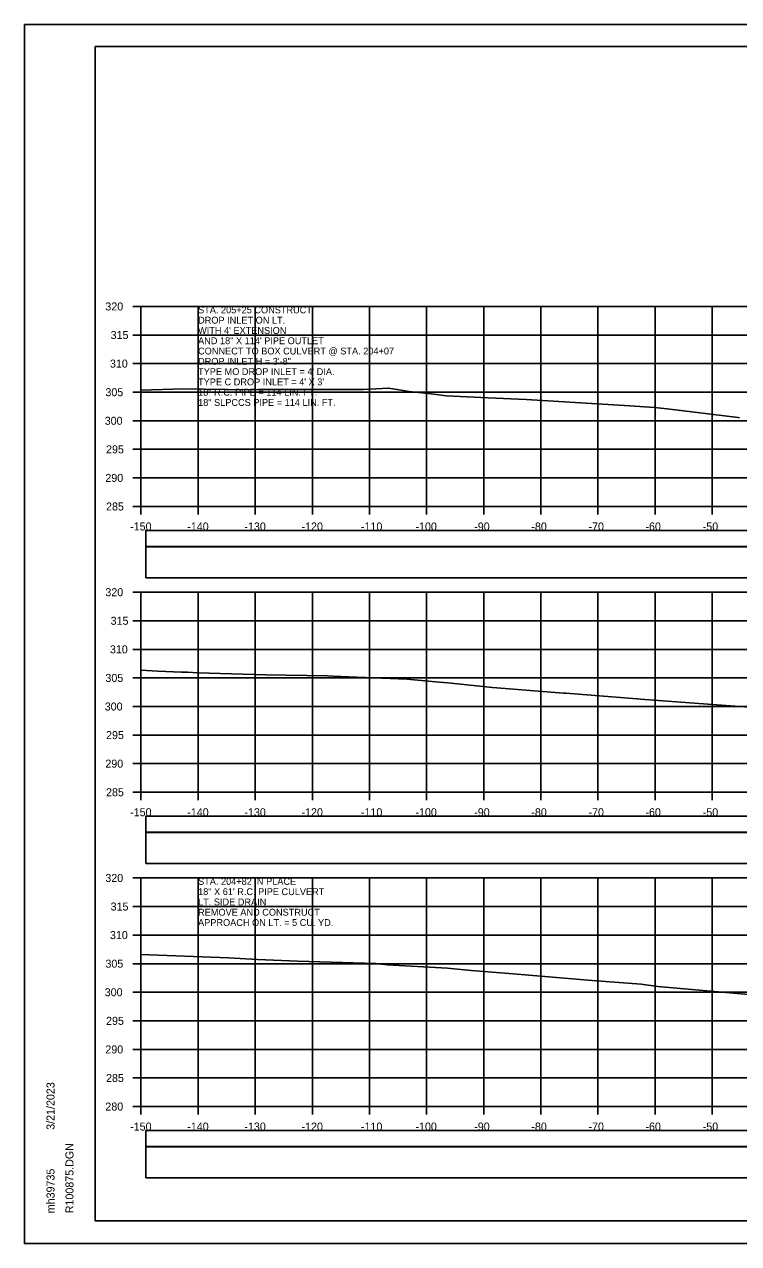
# Model space of a CAD drawing. Extents: x 1368122 to 1710785, y 373130 to 557566.
# Drawn here: x 1369851.8 to 1369976.9, y 373983.7 to 374197 of the extents above; entities that cross this region are included whole.
import ezdxf

# ---------------------------------------------------------------- set-up
doc = ezdxf.new("R2010")
doc.units = 0
for name, color, linetype in [('R_Axis', 7, 'Continuous'), ('R_Axis Annot', 7, 'Continuous'), ('R_Border', 7, 'Continuous'), ('R_Exist Surface', 7, 'Continuous'), ('R_Grid', 7, 'Continuous'), ('R_No Plot', 7, 'Continuous'), ('R_Water Annot', 7, 'Continuous')]:
    doc.layers.add(name, color=color, linetype=linetype)

msp = doc.modelspace()

# ---------------------------------------------------------------- linework, layer by layer
for points in [[(1369873.09, 374105.65), (1370171.39, 374105.65), (1370171.39, 374108.47), (1369873.09, 374108.47)], [(1369873.09, 374100.19), (1370171.39, 374100.19), (1370171.39, 374105.6), (1369873.09, 374105.6)], [(1369873.09, 374055.65), (1370171.39, 374055.65), (1370171.39, 374058.47), (1369873.09, 374058.47)], [(1369873.09, 374050.19), (1370171.39, 374050.19), (1370171.39, 374055.6), (1369873.09, 374055.6)], [(1369873.09, 374000.65), (1370171.39, 374000.65), (1370171.39, 374003.47), (1369873.09, 374003.47)], [(1369873.09, 373995.19), (1370171.39, 373995.19), (1370171.39, 374000.6), (1369873.09, 374000.6)]]:
    msp.add_lwpolyline(points, close=True)
at = {"layer": 'R_Axis'}
for p, q in [((1369870.84, 374147.66), (1369872.24, 374147.66)), ((1369872.24, 374112.66), (1369872.24, 374147.66)), ((1369870.84, 374142.66), (1369872.24, 374142.66)), ((1369870.84, 374137.66), (1369872.24, 374137.66)), ((1369870.84, 374132.66), (1369872.24, 374132.66)), ((1369870.84, 374127.66), (1369872.24, 374127.66)), ((1369870.84, 374122.66), (1369872.24, 374122.66)), ((1369870.84, 374117.66), (1369872.24, 374117.66)), ((1369870.84, 374112.66), (1369872.24, 374112.66)), ((1369872.24, 374112.66), (1370172.24, 374112.66)), ((1369872.24, 374111.26), (1369872.24, 374112.66)), ((1369882.24, 374111.26), (1369882.24, 374112.66)), ((1369892.24, 374111.26), (1369892.24, 374112.66)), ((1369902.24, 374111.26), (1369902.24, 374112.66)), ((1369912.24, 374111.26), (1369912.24, 374112.66)), ((1369922.24, 374111.26), (1369922.24, 374112.66)), ((1369932.24, 374111.26), (1369932.24, 374112.66)), ((1369942.24, 374111.26), (1369942.24, 374112.66)), ((1369952.24, 374111.26), (1369952.24, 374112.66)), ((1369962.24, 374111.26), (1369962.24, 374112.66)), ((1369972.24, 374111.26), (1369972.24, 374112.66)), ((1369870.84, 374097.66), (1369872.24, 374097.66)), ((1369872.24, 374062.66), (1369872.24, 374097.66)), ((1369870.84, 374092.66), (1369872.24, 374092.66)), ((1369870.84, 374087.66), (1369872.24, 374087.66)), ((1369870.84, 374082.66), (1369872.24, 374082.66)), ((1369870.84, 374077.66), (1369872.24, 374077.66)), ((1369870.84, 374072.66), (1369872.24, 374072.66)), ((1369870.84, 374067.66), (1369872.24, 374067.66)), ((1369870.84, 374062.66), (1369872.24, 374062.66)), ((1369872.24, 374062.66), (1370172.24, 374062.66)), ((1369872.24, 374061.26), (1369872.24, 374062.66)), ((1369882.24, 374061.26), (1369882.24, 374062.66)), ((1369892.24, 374061.26), (1369892.24, 374062.66)), ((1369902.24, 374061.26), (1369902.24, 374062.66)), ((1369912.24, 374061.26), (1369912.24, 374062.66)), ((1369922.24, 374061.26), (1369922.24, 374062.66)), ((1369932.24, 374061.26), (1369932.24, 374062.66)), ((1369942.24, 374061.26), (1369942.24, 374062.66)), ((1369952.24, 374061.26), (1369952.24, 374062.66)), ((1369962.24, 374061.26), (1369962.24, 374062.66)), ((1369972.24, 374061.26), (1369972.24, 374062.66)), ((1369870.84, 374047.66), (1369872.24, 374047.66)), ((1369872.24, 374007.66), (1369872.24, 374047.66)), ((1369870.84, 374042.66), (1369872.24, 374042.66)), ((1369870.84, 374037.66), (1369872.24, 374037.66)), ((1369870.84, 374032.66), (1369872.24, 374032.66)), ((1369870.84, 374027.66), (1369872.24, 374027.66)), ((1369870.84, 374022.66), (1369872.24, 374022.66)), ((1369870.84, 374017.66), (1369872.24, 374017.66)), ((1369870.84, 374012.66), (1369872.24, 374012.66)), ((1369870.84, 374007.66), (1369872.24, 374007.66)), ((1369872.24, 374007.66), (1370172.24, 374007.66)), ((1369872.24, 374006.26), (1369872.24, 374007.66)), ((1369882.24, 374006.26), (1369882.24, 374007.66)), ((1369892.24, 374006.26), (1369892.24, 374007.66)), ((1369902.24, 374006.26), (1369902.24, 374007.66)), ((1369912.24, 374006.26), (1369912.24, 374007.66)), ((1369922.24, 374006.26), (1369922.24, 374007.66)), ((1369932.24, 374006.26), (1369932.24, 374007.66)), ((1369942.24, 374006.26), (1369942.24, 374007.66)), ((1369952.24, 374006.26), (1369952.24, 374007.66)), ((1369962.24, 374006.26), (1369962.24, 374007.66)), ((1369972.24, 374006.26), (1369972.24, 374007.66))]:
    msp.add_line(p, q, dxfattribs=at)
at = {"layer": 'R_Border'}
for p, q in [((1369864.24, 374193.12), (1370180.42, 374193.12)), ((1369864.24, 373987.66), (1369864.24, 374193.12)), ((1369864.24, 373987.66), (1369864.24, 373987.66)), ((1370180.42, 373987.66), (1369864.24, 373987.66))]:
    msp.add_line(p, q, dxfattribs=at)
at = {"layer": 'R_Exist Surface'}
for points in [[(1369872.24, 374133.01), (1369879.72, 374133.24), (1369890.47, 374133.06), (1369892.77, 374133.1), (1369895.66, 374133.14), (1369907.83, 374133.12), (1369910.07, 374133.13), (1369910.57, 374133.12), (1369911.14, 374133.14), (1369915.58, 374133.38), (1369917.07, 374133.1), (1369919.19, 374132.76), (1369923.02, 374132.36), (1369925.67, 374132.04), (1369933.04, 374131.7), (1369939.66, 374131.38), (1369947.34, 374130.94), (1369957.8, 374130.3), (1369962.12, 374130), (1369964.38, 374129.75), (1369976.8, 374128.21), (1369977.02, 374128.17)], [(1369872.24, 374084), (1369875.22, 374083.87), (1369879.32, 374083.69), (1369880.14, 374083.68), (1369880.39, 374083.66), (1369882.2, 374083.58), (1369890.07, 374083.34), (1369894.05, 374083.21), (1369904.87, 374083.02), (1369905.91, 374082.94), (1369914.32, 374082.62), (1369918.86, 374082.47), (1369924.43, 374081.89), (1369925.97, 374081.8), (1369933.77, 374080.97), (1369946.18, 374080.01), (1369946.63, 374079.97), (1369959.1, 374079), (1369959.18, 374078.99), (1369959.67, 374078.95), (1369974.63, 374077.81), (1369978.79, 374077.52)], [(1369872.24, 374034.26), (1369887.56, 374033.69), (1369892.66, 374033.4), (1369899.65, 374033.12), (1369913.38, 374032.67), (1369915.34, 374032.47), (1369925.91, 374031.89), (1369930.07, 374031.44), (1369936.69, 374030.93), (1369951.22, 374029.72), (1369959.79, 374029.05), (1369962.73, 374028.64), (1369979.92, 374027.15)]]:
    msp.add_lwpolyline(points, dxfattribs=at)
at = {"layer": 'R_Grid'}
for p, q in [((1369872.24, 374147.66), (1370172.24, 374147.66)), ((1369872.24, 374112.66), (1369872.24, 374147.66)), ((1369882.24, 374112.66), (1369882.24, 374147.66)), ((1369892.24, 374112.66), (1369892.24, 374147.66)), ((1369902.24, 374112.66), (1369902.24, 374147.66)), ((1369912.24, 374112.66), (1369912.24, 374147.66)), ((1369922.24, 374112.66), (1369922.24, 374147.66)), ((1369932.24, 374112.66), (1369932.24, 374147.66)), ((1369942.24, 374112.66), (1369942.24, 374147.66)), ((1369952.24, 374112.66), (1369952.24, 374147.66)), ((1369962.24, 374112.66), (1369962.24, 374147.66)), ((1369972.24, 374112.66), (1369972.24, 374147.66)), ((1369872.24, 374142.66), (1370172.24, 374142.66)), ((1369872.24, 374137.66), (1370172.24, 374137.66)), ((1369872.24, 374132.66), (1370172.24, 374132.66)), ((1369872.24, 374127.66), (1370172.24, 374127.66)), ((1369872.24, 374122.66), (1370172.24, 374122.66)), ((1369872.24, 374117.66), (1370172.24, 374117.66)), ((1369872.24, 374112.66), (1370172.24, 374112.66)), ((1369872.24, 374097.66), (1370172.24, 374097.66)), ((1369872.24, 374062.66), (1369872.24, 374097.66)), ((1369882.24, 374062.66), (1369882.24, 374097.66)), ((1369892.24, 374062.66), (1369892.24, 374097.66)), ((1369902.24, 374062.66), (1369902.24, 374097.66)), ((1369912.24, 374062.66), (1369912.24, 374097.66)), ((1369922.24, 374062.66), (1369922.24, 374097.66)), ((1369932.24, 374062.66), (1369932.24, 374097.66)), ((1369942.24, 374062.66), (1369942.24, 374097.66)), ((1369952.24, 374062.66), (1369952.24, 374097.66)), ((1369962.24, 374062.66), (1369962.24, 374097.66)), ((1369972.24, 374062.66), (1369972.24, 374097.66)), ((1369872.24, 374092.66), (1370172.24, 374092.66)), ((1369872.24, 374087.66), (1370172.24, 374087.66)), ((1369872.24, 374082.66), (1370172.24, 374082.66)), ((1369872.24, 374077.66), (1370172.24, 374077.66)), ((1369872.24, 374072.66), (1370172.24, 374072.66)), ((1369872.24, 374067.66), (1370172.24, 374067.66)), ((1369872.24, 374062.66), (1370172.24, 374062.66)), ((1369872.24, 374047.66), (1370172.24, 374047.66)), ((1369872.24, 374007.66), (1369872.24, 374047.66)), ((1369882.24, 374007.66), (1369882.24, 374047.66)), ((1369892.24, 374007.66), (1369892.24, 374047.66)), ((1369902.24, 374007.66), (1369902.24, 374047.66)), ((1369912.24, 374007.66), (1369912.24, 374047.66)), ((1369922.24, 374007.66), (1369922.24, 374047.66)), ((1369932.24, 374007.66), (1369932.24, 374047.66)), ((1369942.24, 374007.66), (1369942.24, 374047.66)), ((1369952.24, 374007.66), (1369952.24, 374047.66)), ((1369962.24, 374007.66), (1369962.24, 374047.66)), ((1369972.24, 374007.66), (1369972.24, 374047.66)), ((1369872.24, 374042.66), (1370172.24, 374042.66)), ((1369872.24, 374037.66), (1370172.24, 374037.66)), ((1369872.24, 374032.66), (1370172.24, 374032.66)), ((1369872.24, 374027.66), (1370172.24, 374027.66)), ((1369872.24, 374022.66), (1370172.24, 374022.66)), ((1369872.24, 374017.66), (1370172.24, 374017.66)), ((1369872.24, 374012.66), (1370172.24, 374012.66)), ((1369872.24, 374007.66), (1370172.24, 374007.66))]:
    msp.add_line(p, q, dxfattribs=at)
at = {"layer": 'R_No Plot'}
for p, q in [((1369851.84, 374197.02), (1370185.17, 374197.02)), ((1369851.84, 373983.68), (1370185.17, 373983.68))]:
    msp.add_line(p, q, dxfattribs=at)
for points in [[(1369851.83, 374197.02), (1370185.17, 374197.02), (1370185.17, 373983.68), (1369851.83, 373983.68)], [(1370098.16, 374193.12), (1370117.78, 374193.12), (1370117.78, 374183.24), (1370133.89, 374183.24), (1370157.09, 374183.24), (1370157.21, 374155.08), (1370180.42, 374155.08), (1370180.42, 373987.66), (1369864.24, 373987.66), (1369864.24, 374193.12)]]:
    msp.add_lwpolyline(points, close=True, dxfattribs=at)

# ---------------------------------------------------------------- texts
at = {"layer": 'R_Axis Annot'}
for s, p in [('320', (1369866.01, 374146.96)), ('315', (1369866.93, 374141.96)), ('310', (1369866.81, 374136.96)), ('305', (1369866.02, 374131.96)), ('300', (1369865.9, 374126.96)), ('295', (1369866.13, 374121.96)), ('290', (1369866.01, 374116.96)), ('285', (1369866.13, 374111.96)), ('-150', (1369870.35, 374108.46)), ('-140', (1369880.35, 374108.46)), ('-130', (1369890.35, 374108.46)), ('-120', (1369900.35, 374108.46)), ('-110', (1369910.75, 374108.46)), ('-100', (1369920.29, 374108.46)), ('-90', (1369930.58, 374108.46)), ('-80', (1369940.58, 374108.46)), ('-70', (1369950.58, 374108.46)), ('-60', (1369960.55, 374108.46)), ('-50', (1369970.58, 374108.46)), ('320', (1369866.01, 374096.96)), ('315', (1369866.93, 374091.96)), ('310', (1369866.81, 374086.96)), ('305', (1369866.02, 374081.96)), ('300', (1369865.9, 374076.96)), ('295', (1369866.13, 374071.96)), ('290', (1369866.01, 374066.96)), ('285', (1369866.13, 374061.96)), ('-150', (1369870.35, 374058.46)), ('-140', (1369880.35, 374058.46)), ('-130', (1369890.35, 374058.46)), ('-120', (1369900.35, 374058.46)), ('-110', (1369910.75, 374058.46)), ('-100', (1369920.29, 374058.46)), ('-90', (1369930.58, 374058.46)), ('-80', (1369940.58, 374058.46)), ('-70', (1369950.58, 374058.46)), ('-60', (1369960.55, 374058.46)), ('-50', (1369970.58, 374058.46)), ('320', (1369866.01, 374046.96)), ('315', (1369866.93, 374041.96)), ('310', (1369866.81, 374036.96)), ('305', (1369866.02, 374031.96)), ('300', (1369865.9, 374026.96)), ('295', (1369866.13, 374021.96)), ('290', (1369866.01, 374016.96)), ('285', (1369866.13, 374011.96)), ('280', (1369866.01, 374006.96)), ('-150', (1369870.35, 374003.46)), ('-140', (1369880.35, 374003.46)), ('-130', (1369890.35, 374003.46)), ('-120', (1369900.35, 374003.46)), ('-110', (1369910.75, 374003.46)), ('-100', (1369920.29, 374003.46)), ('-90', (1369930.58, 374003.46)), ('-80', (1369940.58, 374003.46)), ('-70', (1369950.58, 374003.46)), ('-60', (1369960.55, 374003.46)), ('-50', (1369970.58, 374003.46))]:
    msp.add_text(s, height=1.4, dxfattribs=at).set_placement(p)
at = {"layer": 'R_Border'}
for s, p in [('3/21/2023', (1369857.11, 374003.59)), ('R100875.DGN', (1369860.43, 373988.99)), ('mh39735', (1369857.11, 373988.99))]:
    msp.add_text(s, height=1.4, rotation=90, dxfattribs=at).set_placement(p)
at = {"layer": 'R_Water Annot'}
for s, p in [('STA. 205+25 CONSTRUCT', (1369882.24, 374146.46)), ('DROP INLET ON LT.', (1369882.24, 374144.66)), ("WITH 4' EXTENSION", (1369882.24, 374142.86)), ('AND 18" X 114\' PIPE OUTLET', (1369882.24, 374141.06)), ('CONNECT TO BOX CULVERT @ STA. 204+07', (1369882.24, 374139.26)), ("TYPE MO DROP INLET = 4' DIA.", (1369882.24, 374135.66)), ('DROP INLET H = 3\'-8"', (1369882.24, 374137.46)), ("TYPE C DROP INLET = 4' X 3'", (1369882.24, 374133.86)), ('18" R.C. PIPE = 114 LIN. FT.', (1369882.24, 374132.06)), ('18" SLPCCS PIPE = 114 LIN. FT.', (1369882.24, 374130.26)), ('STA. 204+82 IN PLACE', (1369882.24, 374046.46)), ('18" X 61\' R.C. PIPE CULVERT', (1369882.24, 374044.66)), ('LT. SIDE DRAIN', (1369882.24, 374042.86)), ('REMOVE AND CONSTRUCT', (1369882.24, 374041.06)), ('APPROACH ON LT. = 5 CU. YD.', (1369882.24, 374039.26))]:
    msp.add_text(s, height=1.2, dxfattribs=at).set_placement(p)

doc.saveas('drawing.dxf')
